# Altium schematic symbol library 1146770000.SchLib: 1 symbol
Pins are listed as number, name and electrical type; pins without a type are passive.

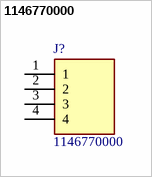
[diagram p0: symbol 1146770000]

## 1146770000
designator J?
PCB plug-in connector, male header, open side, THT solder connection, 5.08 mm, Number of poles: 4, 90, Solder pin length: 3.2 mm, tinned, orange, Box; Manufacturer_Name: Weidmuller; Geometry.Height: 8.4mm
footprint 1146770000
pins: 1, 2, 3, 4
